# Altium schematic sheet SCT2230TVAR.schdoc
size 127 x 101 mm
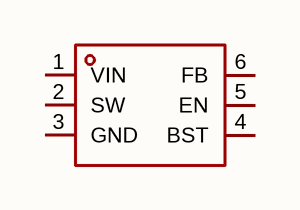
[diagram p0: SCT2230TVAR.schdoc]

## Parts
U?  sct2230atvar  [SOT-563_L1.6-W1.2-P0.50-LS1.6-BL]  (value not drawn)

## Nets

Not connected (* = marked no-connect by the designer): U? 1(VIN) 2(SW) 3(GND) 4(BST) 5(EN) 6(FB)

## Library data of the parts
U? = sct2230atvar: 功能类型:降压型;工作电压:4.2V~17V;输出电压:800mV~7V;输出电流:3A;输出类型:可调;; Manufacturer: SCT(芯洲科技); Symbol: SCT2230TVAR; AddInBom: yes; ModelId: ae4c13e967cf4f598e77975e9d61b1bf; ModelName: SOT-563-6P_L1.6-W1.2-H0.6-LS1.6-P0.50; ModelTransform: 62.992,62.992,0,90,0,0,-0.005,0.005,0; Function: 降压型; Output Current: 3A; Frequency - Switching: 750kHz; Synchronous Rectifier: 是; Number of Outputs: 1; Topology: 降压式; Quiescent Current: 150uA; Switch tube (built-in/external): 内置; Output Type: 可调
